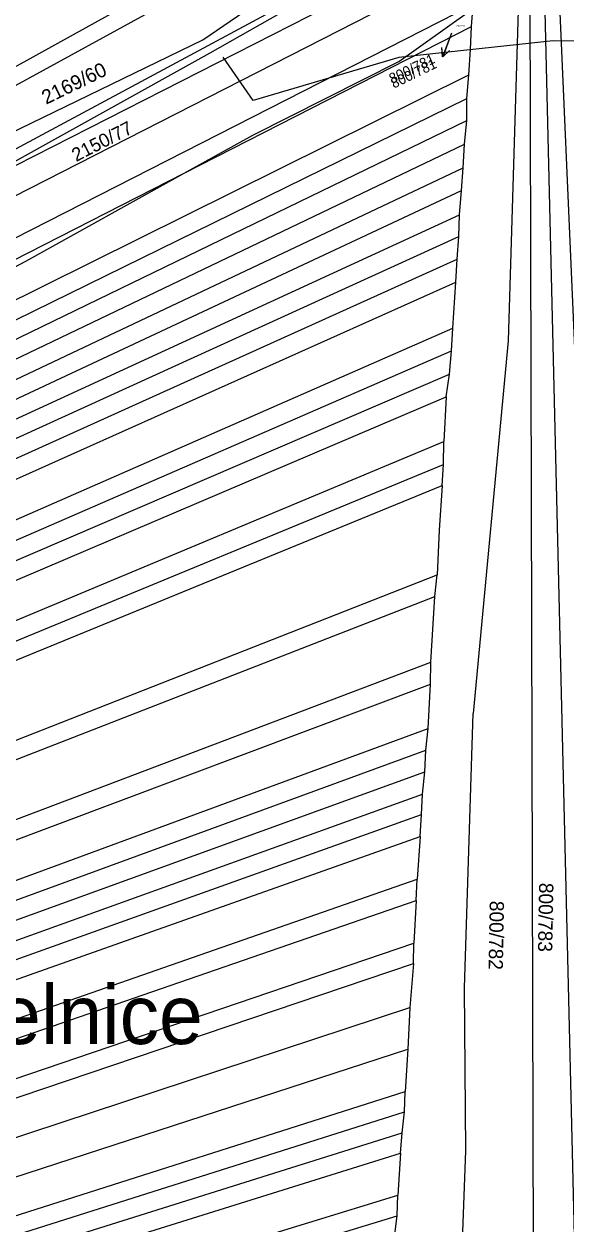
# Model space of a CAD drawing. Extents: x -555860 to -552701, y -1187050 to -1182291.
# Drawn here: x -554737.1 to -554672.6, y -1185587.5 to -1185444.8 of the extents above; entities that cross this region are included whole.
import ezdxf

# ---------------------------------------------------------------- set-up
doc = ezdxf.new("R2010")
doc.units = 0
for name, color, linetype in [('LEG_2b', 7, 'Continuous'), ('Level 16', 7, 'Continuous'), ('Level 32', 7, 'Continuous'), ('Level 40', 7, 'Continuous'), ('Level 41', 7, 'Continuous'), ('navrh_BV', 7, 'Continuous'), ('Parcelní čísla', 7, 'Continuous'), ('stav_BV', 7, 'Continuous')]:
    doc.layers.add(name, color=color, linetype=linetype)

msp = doc.modelspace()

# ---------------------------------------------------------------- linework, layer by layer
at = {"layer": 'Level 16'}
for p, q in [((-554686.22, -1185445.88), (-554687.28, -1185448.69)), ((-554687.28, -1185448.69), (-554687.39, -1185447.58)), ((-554687.28, -1185448.69), (-554686.46, -1185447.93))]:
    msp.add_line(p, q, dxfattribs=at)
at = {"layer": 'Level 32'}
msp.add_lwpolyline([(-554698.05, -1185438.6), (-554714.96, -1185448.24), (-554741.93, -1185463.25), (-554750.17, -1185467.82), (-554773.94, -1185481.01), (-554777.58, -1185473.79), (-554783.65, -1185463.15), (-554790.07, -1185451.89), (-554786.97, -1185444.66)], dxfattribs=at)
at = {"layer": 'Level 40'}
msp.add_lwpolyline([(-554597.66, -1185587.3), (-554596.84, -1185584.89), (-554589.36, -1185556.6), (-554585.47, -1185528.31), (-554578.12, -1185485.89), (-554577.15, -1185476.46), (-554577.99, -1185467.03), (-554579.23, -1185462.31), (-554581.59, -1185457.6), (-554587, -1185450.53), (-554590.74, -1185447.89), (-554596.01, -1185445.4), (-554605.44, -1185443.32), (-554614.87, -1185443.46), (-554641.62, -1185446.35), (-554658.14, -1185446.82), (-554674.17, -1185446.79), (-554692.5, -1185448.77), (-554709.81, -1185453.88), (-554713.38, -1185448.73)], dxfattribs=at)
at = {"layer": 'Level 41'}
msp.add_lwpolyline([(-554871.41, -1185304.71), (-554871.04, -1185319.22), (-554873.45, -1185336.56), (-554879.64, -1185354.6), (-554880.53, -1185368.5), (-554877.6, -1185382.58), (-554873.3, -1185396.32), (-554862.7, -1185410.01), (-554853.22, -1185420.99), (-554839.21, -1185442.35), (-554833.95, -1185452.05), (-554823.27, -1185465.09), (-554814.61, -1185472.65), (-554810.64, -1185474.15), (-554800.31, -1185473.8), (-554782, -1185470.03), (-554761.13, -1185462.61), (-554710.48, -1185434.53), (-554672.53, -1185409.41), (-554665.16, -1185406.66), (-554661.47, -1185407.95)], dxfattribs=at)
at = {"layer": 'navrh_BV'}
for p, q in [((-554689.29, -1185433.35), (-554800.95, -1185493.61)), ((-554683.08, -1185433.59), (-554750.17, -1185467.82)), ((-554715.8, -1185446.65), (-554699.63, -1185435.59)), ((-554803.46, -1185498.58), (-554683.26, -1185437.19)), ((-554711.78, -1185437.68), (-554777.58, -1185473.79)), ((-554675.27, -1185438.16), (-554670.94, -1185619.06)), ((-554665.82, -1185615.77), (-554673.6, -1185437.2)), ((-554676.43, -1185622.47), (-554676.89, -1185439.1)), ((-554804.42, -1185504.06), (-554683.68, -1185442.47)), ((-554692.49, -1185449.24), (-554684.1, -1185443.27)), ((-554683.85, -1185445.08), (-554683.72, -1185443.05)), ((-554678.3, -1185443.18), (-554679.52, -1185482.49)), ((-554718.03, -1185462.53), (-554683.85, -1185445.08)), ((-554683.99, -1185447.83), (-554683.85, -1185445.08)), ((-554743.55, -1185460.15), (-554715.8, -1185446.65)), ((-554684.18, -1185450.82), (-554683.99, -1185447.83)), ((-554709.87, -1185457.99), (-554692.49, -1185449.24)), ((-554805.59, -1185511.17), (-554684.18, -1185450.82)), ((-554684.41, -1185453.64), (-554684.18, -1185450.82)), ((-554805.87, -1185513.31), (-554684.41, -1185453.64)), ((-554684.4, -1185456.26), (-554684.41, -1185453.64)), ((-554806.33, -1185515.48), (-554684.4, -1185456.26)), ((-554684.71, -1185459.08), (-554684.4, -1185456.26)), ((-554718.03, -1185462.53), (-554709.87, -1185457.99)), ((-554806.69, -1185517.56), (-554684.71, -1185459.08)), ((-554684.86, -1185461.9), (-554684.71, -1185459.08)), ((-554807.1, -1185519.8), (-554684.86, -1185461.9)), ((-554685.04, -1185464.6), (-554684.86, -1185461.9)), ((-554804.88, -1185506.88), (-554718.03, -1185462.53)), ((-554736.83, -1185473), (-554718.03, -1185462.53)), ((-554807.42, -1185521.93), (-554685.04, -1185464.6)), ((-554685.28, -1185467.47), (-554685.04, -1185464.6)), ((-554807.75, -1185523.9), (-554685.28, -1185467.47)), ((-554685.37, -1185470.07), (-554685.28, -1185467.47)), ((-554808.11, -1185526.08), (-554685.37, -1185470.07)), ((-554685.58, -1185472.75), (-554685.37, -1185470.07)), ((-554808.59, -1185528.38), (-554685.58, -1185472.75)), ((-554769.17, -1185490.14), (-554736.83, -1185473)), ((-554685.72, -1185475.49), (-554685.58, -1185472.75)), ((-554808.84, -1185530.68), (-554685.72, -1185475.49)), ((-554686.09, -1185480.99), (-554685.72, -1185475.49)), ((-554809.49, -1185535.15), (-554686.09, -1185480.99)), ((-554686.25, -1185483.67), (-554686.09, -1185480.99)), ((-554809.74, -1185537.39), (-554686.25, -1185483.67)), ((-554686.47, -1185486.44), (-554686.25, -1185483.67)), ((-554679.52, -1185482.49), (-554683.68, -1185526.81)), ((-554810.05, -1185539.64), (-554686.47, -1185486.44)), ((-554686.86, -1185489.13), (-554686.47, -1185486.44)), ((-554810.34, -1185541.87), (-554686.86, -1185489.13)), ((-554686.86, -1185489.13), (-554687.16, -1185494.46)), ((-554811.04, -1185546.3), (-554687.16, -1185494.46)), ((-554687.2, -1185497.19), (-554687.16, -1185494.46)), ((-554811.32, -1185548.44), (-554687.2, -1185497.19)), ((-554687.34, -1185499.7), (-554687.2, -1185497.19)), ((-554811.61, -1185550.67), (-554687.34, -1185499.7)), ((-554687.34, -1185499.7), (-554687.72, -1185505.02)), ((-554687.72, -1185505.02), (-554687.93, -1185510.33)), ((-554812.84, -1185559.41), (-554687.93, -1185510.33)), ((-554688.2, -1185512.92), (-554687.93, -1185510.33)), ((-554813.16, -1185561.56), (-554688.2, -1185512.92)), ((-554688.68, -1185520.72), (-554688.2, -1185512.92)), ((-554813.94, -1185568.21), (-554688.68, -1185520.72)), ((-554688.73, -1185523.33), (-554688.68, -1185520.72)), ((-554814.15, -1185570.44), (-554688.73, -1185523.33)), ((-554689, -1185528.59), (-554688.73, -1185523.33)), ((-554684.68, -1185559.45), (-554683.68, -1185526.81)), ((-554814.61, -1185574.92), (-554689, -1185528.59)), ((-554689.27, -1185531.19), (-554689, -1185528.59)), ((-554814.87, -1185577.12), (-554689.27, -1185531.19)), ((-554689.4, -1185533.75), (-554689.27, -1185531.19)), ((-554815.07, -1185579.4), (-554689.4, -1185533.75)), ((-554689.69, -1185536.43), (-554689.4, -1185533.75)), ((-554815.32, -1185581.68), (-554689.69, -1185536.43)), ((-554689.79, -1185538.86), (-554689.69, -1185536.43)), ((-554815.56, -1185583.84), (-554689.79, -1185538.86)), ((-554689.98, -1185541.48), (-554689.79, -1185538.86)), ((-554815.74, -1185586.04), (-554689.98, -1185541.48)), ((-554689.98, -1185541.48), (-554690.31, -1185546.54)), ((-554816.17, -1185590.43), (-554690.31, -1185546.54)), ((-554690.44, -1185549.09), (-554690.31, -1185546.54)), ((-554816.44, -1185592.67), (-554690.44, -1185549.09)), ((-554690.44, -1185549.09), (-554690.73, -1185554.14)), ((-554816.83, -1185597.07), (-554690.73, -1185554.14)), ((-554690.77, -1185556.59), (-554690.73, -1185554.14)), ((-554817.1, -1185599.28), (-554690.77, -1185556.59)), ((-554690.77, -1185556.59), (-554691.18, -1185561.79)), ((-554684.54, -1185578.86), (-554684.68, -1185559.45)), ((-554817.52, -1185603.53), (-554691.18, -1185561.79)), ((-554691.18, -1185561.79), (-554691.43, -1185566.77)), ((-554817.91, -1185607.94), (-554691.43, -1185566.77)), ((-554691.43, -1185566.77), (-554691.76, -1185571.79)), ((-554818.27, -1185612.23), (-554691.76, -1185571.79)), ((-554691.83, -1185574.23), (-554691.76, -1185571.79)), ((-554818.46, -1185614.37), (-554691.83, -1185574.23)), ((-554692.11, -1185576.72), (-554691.83, -1185574.23)), ((-554818.67, -1185616.5), (-554692.11, -1185576.72)), ((-554692.29, -1185579.13), (-554692.11, -1185576.72)), ((-554818.93, -1185618.72), (-554692.29, -1185579.13)), ((-554692.29, -1185579.13), (-554692.62, -1185584.15)), ((-554685.36, -1185601.97), (-554684.54, -1185578.86)), ((-554819.36, -1185622.91), (-554692.62, -1185584.15)), ((-554692.69, -1185586.61), (-554692.62, -1185584.15)), ((-554819.52, -1185625), (-554692.69, -1185586.61)), ((-554693.03, -1185589.09), (-554692.69, -1185586.61))]:
    msp.add_line(p, q, dxfattribs=at)
at = {"layer": 'stav_BV'}
for p, q in [((-554686.22, -1185445.88), (-554687.3, -1185448.68)), ((-554687.3, -1185448.68), (-554687.4, -1185447.57)), ((-554687.3, -1185448.68), (-554686.47, -1185447.93))]:
    msp.add_line(p, q, dxfattribs=at)

# ---------------------------------------------------------------- texts
at = {"layer": 'LEG_2b'}
msp.add_text('800/781', height=0.2, dxfattribs=at).set_placement((-554685.63, -1185445.11))
for s, height, rotation, p in [('2169/60', 1.7, 26, (-554734.43, -1185454.4)), ('800/781', 1.2, 26, (-554693.09, -1185452.48)), ('2150/77', 1.6, 27, (-554730.86, -1185461.21)), ('800/783', 1.7, 269, (-554675.82, -1185546.96)), ('800/782', 1.7, 269, (-554681.69, -1185549.1))]:
    msp.add_text(s, height=height, rotation=rotation, dxfattribs=at).set_placement(p)
at = {"layer": 'Level 16'}
msp.add_text('800/781', height=1.2, rotation=26.1, dxfattribs=at).set_placement((-554693.29, -1185451.9))
at = {"layer": 'Parcelní čísla'}
msp.add_text('Úzké zelnice', height=7, dxfattribs=at).set_placement((-554768.86, -1185566.16))

doc.saveas('drawing.dxf')
